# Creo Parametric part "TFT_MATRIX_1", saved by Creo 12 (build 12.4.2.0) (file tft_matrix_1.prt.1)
Units: Custom; MM, KILOGRAM, SECS

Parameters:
  PTC_WM_ITERATION = "0"
  PTC_WM_VERSION = "-.0"
  PTC_WM_LIFECYCLE_STATE = "In Work"
  PTC_WM_LIFECYCLE = "MO_CADDocument"
  PTC_WM_CREATED_BY = "Maximilian Roepper (Z0017RMS: MO)"
  PTC_WM_CREATED_ON = "18-Sep-26 11:36:42 AM"
  PTC_WM_MODIFIED_BY = "Maximilian Roepper (Z0017RMS: MO)"
  PTC_WM_MODIFIED_ON = "18-Sep-26 11:36:46 AM"
  PDMLINKNUMBER = "PDM000071454931"
  PTC_WM_NAME = "tft_matrix_1.prt"
  PTC_WM_NUMBER = "PDM000071454931"

Other parameters: WEIGHT, WEIGHT_FACTOR, WEIGHT_ADD, _MASS_TEMP, _DIFF_TEMP, MC_ERRORS, SUPPLIER

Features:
  1. coordinate system
  2. datum plane "PRT_YZ"
  3. datum plane "PRT_XY"
  4. datum plane "PRT_XZ"
  5. coordinate system
  6. datum axis
  7. datum axis
  8. datum axis
  9. coordinate system
  10. imported feature

Other named items: PRT, SIEMENS_MO, DRW_VIEW_ORG, PRT_X, PRT_Y, PRT_Z, CS0, ROUGH_GROB

Layers: 00_STD_CSYS-KSYS, 01_STD_PLANES-EBENEN, 02_STD_AXES-ACHSEN, 03_STD_CSYS-KSYS, 24_IMPORT_FEAT-IMPORT_KE

Surfaces: 6 plane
